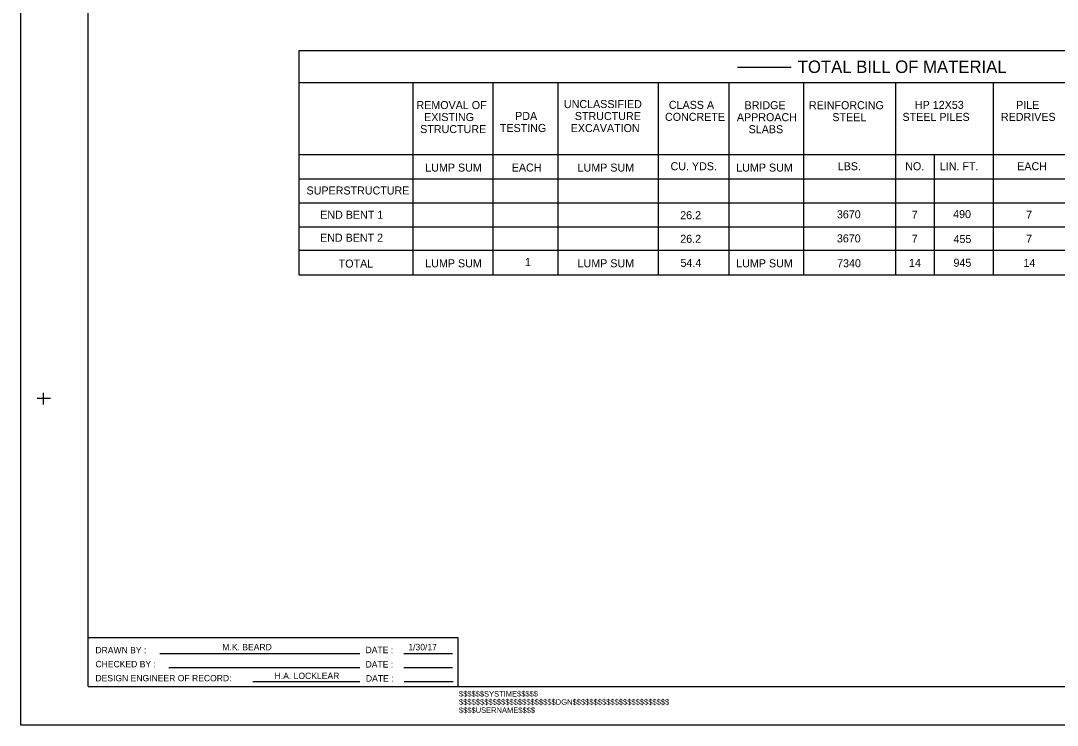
# Model space of a CAD drawing. Extents: x -20 to 509, y -659 to 21.
# Drawn here: x -19.9 to 239.1, y -658.9 to -482.9 of the extents above; entities that cross this region are included whole.
import ezdxf

# ---------------------------------------------------------------- set-up
doc = ezdxf.new("R2010")
doc.units = 0
for name, color, linetype in [('Default', 7, 'Continuous'), ('Plan Sheet CELL', 7, 'Continuous'), ('Plot Label CELL', 7, 'Continuous'), ('Plot Shape CELL', 7, 'Continuous'), ('Subtitle Text', 7, 'Continuous'), ('Text', 7, 'Continuous'), ('Typical Text General CELL', 7, 'Continuous')]:
    doc.layers.add(name, color=color, linetype=linetype)

msp = doc.modelspace()

# ---------------------------------------------------------------- linework, layer by layer
at = {"layer": 'Default'}
for p, q in [((49.55, -490.36), (49.55, -546.38)), ((355.63, -490.36), (49.55, -490.36)), ((265.45, -490.36), (193.73, -490.36)), ((172.62, -494.54), (159.22, -494.54)), ((274.98, -498.35), (49.55, -498.35)), ((139.48, -498.42), (139.48, -498.42)), ((139.48, -498.42), (139.48, -498.42)), ((338.29, -498.35), (198.01, -498.35)), ((49.55, -516.28), (274.98, -516.28)), ((49.55, -516.9), (49.55, -516.9)), ((98.08, -516.27), (169.95, -516.27)), ((139.48, -516.28), (355.63, -516.28)), ((49.55, -546.38), (355.63, -546.38)), ((139.48, -546.44), (139.48, -546.44)), ((139.48, -546.44), (139.48, -546.44))]:
    msp.add_line(p, q, dxfattribs=at)
at = {"layer": 'Plan Sheet CELL'}
for p, q in [((-3.08, -649.17), (-3.08, -313.17)), ((-15.86, -577.17), (-12.5, -577.17)), ((-14.22, -578.75), (-14.22, -575.85)), ((-3.08, -636.98), (89.31, -636.98)), ((89.31, -636.98), (89.31, -649.17)), ((14.82, -640.94), (64.77, -640.94)), ((75.76, -640.94), (88, -640.94)), ((17.11, -644.45), (64.77, -644.45)), ((75.76, -644.45), (88, -644.45)), ((-3.08, -649.17), (508.93, -649.17)), ((38.08, -647.96), (64.77, -647.96)), ((38.08, -647.96), (64.77, -647.96)), ((75.85, -647.96), (88.09, -647.96)), ((75.85, -647.96), (88.09, -647.96)), ((-19.94, -658.86), (-19.94, -658.86))]:
    msp.add_line(p, q, dxfattribs=at)
at = {"layer": 'Plot Shape CELL'}
msp.add_lwpolyline([(-19.94, -306.87), (509.07, -306.87), (509.07, -658.86), (-19.94, -658.86)], close=True, dxfattribs=at)
at = {"layer": 'Typical Text General CELL'}
for p, q in [((78.09, -498.35), (78.09, -546.38)), ((78.09, -498.35), (78.09, -546.38)), ((98.08, -498.35), (98.08, -546.38)), ((98.08, -498.35), (98.08, -546.38)), ((114.27, -498.35), (114.27, -546.38)), ((139.48, -546.38), (139.48, -498.35)), ((157.04, -498.35), (157.04, -546.38)), ((175.68, -498.35), (175.68, -546.38)), ((198.7, -498.35), (198.7, -546.38)), ((198.7, -498.35), (198.7, -546.38)), ((223.09, -498.35), (223.09, -546.38)), ((208.33, -516.28), (208.33, -546.38)), ((49.55, -522.4), (274.98, -522.4)), ((139.48, -522.4), (355.63, -522.4)), ((49.55, -528.33), (274.98, -528.33)), ((139.48, -528.33), (355.63, -528.33)), ((49.55, -534.39), (355.63, -534.39)), ((49.55, -540.19), (274.98, -540.19)), ((139.48, -540.19), (355.63, -540.19))]:
    msp.add_line(p, q, dxfattribs=at)

# ---------------------------------------------------------------- texts
at = {"layer": 'Default'}
for s, height, p in [('TOTAL BILL OF MATERIAL', 3.1223, (174.24, -495.92)), ('REMOVAL OF', 2, (78.96, -504.93)), ('UNCLASSIFIED', 2, (115.81, -504.68)), ('CLASS A', 2, (142.04, -504.88)), ('BRIDGE', 2, (160.95, -504.96)), ('REINFORCING', 2, (177.04, -504.96)), ('HP 12X53', 2, (203.53, -504.88)), ('PILE', 2, (228.82, -504.88)), ('EXISTING', 2, (80.86, -507.93)), ('PDA', 2, (103.62, -507.65)), ('STRUCTURE', 2, (118.54, -507.68)), ('CONCRETE', 2, (141.07, -507.88)), ('APPROACH', 2, (159.03, -507.96)), ('STEEL', 2, (182.89, -507.96)), ('STEEL PILES', 2, (200.42, -507.88)), ('REDRIVES', 2, (225.02, -507.88)), ('STRUCTURE ', 2, (79.89, -510.93)), ('TESTING', 2, (99.8, -510.65)), ('EXCAVATION', 2, (117.5, -510.68)), ('SLABS', 2, (161.97, -510.96)), ('LUMP SUM', 2, (81.16, -520.55)), ('EACH', 2, (102.77, -520.54)), ('LUMP SUM', 2, (119.23, -520.55)), ('CU. YDS.', 2, (142.46, -520.21)), ('LUMP SUM', 2, (158.88, -520.55)), ('LBS.', 2, (184.24, -520.21)), ('NO.', 2, (201.1, -520.21)), ('LIN. FT.', 2, (209.75, -520.21)), ('EACH', 2, (229.1, -520.21)), ('LUMP SUM', 2, (81.16, -544.46)), ('LUMP SUM', 2, (119.23, -544.46)), ('LUMP SUM', 2, (158.88, -544.46))]:
    msp.add_text(s, height=height, dxfattribs=at).set_placement(p)
at = {"layer": 'Plan Sheet CELL'}
for s, height, p in [('DRAWN BY :', 1.6, (-1.27, -640.91)), ('DATE :', 1.6, (66.24, -640.86)), ('CHECKED BY :', 1.5999, (-1.27, -644.38)), ('DATE :', 1.6, (66.24, -644.44)), ('DESIGN ENGINEER OF RECORD:', 1.5999, (-1.27, -647.89)), ('DATE :', 1.6, (66.33, -647.95))]:
    msp.add_text(s, height=height, dxfattribs=at).set_placement(p)
at = {"layer": 'Plot Label CELL'}
for s, height, p in [('$$$$$$SYSTIME$$$$$', 1.3606, (89.58, -651.69)), ('$$$$$$$$$$$$$$$$$$$$$$$DGN$$$$$$$$$$$$$$$$$$$$$$$', 1.3689, (89.58, -653.73)), ('$$$$USERNAME$$$$', 1.3606, (89.58, -655.77))]:
    msp.add_text(s, height=height, dxfattribs=at).set_placement(p)
at = {"layer": 'Subtitle Text'}
for s, height, p in [('M.K. BEARD', 1.6, (30.44, -640.13)), ('1/30/17', 1.6, (76.93, -640.13)), ('H.A. LOCKLEAR', 1.5999, (43.51, -647.32))]:
    msp.add_text(s, height=height, dxfattribs=at).set_placement(p)
at = {"layer": 'Text'}
for s, p in [('26.2', (144.88, -532.45)), ('3670', (184.02, -532.23)), ('7', (202.71, -532.34)), ('490', (213.08, -532.17)), ('7', (231.32, -532.34)), ('3670', (184.02, -538.24)), ('26.2', (144.88, -538.34)), ('7', (202.71, -538.34)), ('455', (213.17, -538.4)), ('7', (231.32, -538.34)), ('1', (106.05, -544.17)), ('54.4', (144.94, -544.35)), ('7340', (184.08, -544.45)), ('14', (202.05, -544.35)), ('945', (213.16, -544.32)), ('14', (230.66, -544.35))]:
    msp.add_text(s, height=2, dxfattribs=at).set_placement(p)
at = {"layer": 'Typical Text General CELL'}
for s, p in [('SUPERSTRUCTURE', (51.49, -526.27)), ('END BENT 1', (54.9, -532.33)), ('END BENT 2', (54.87, -538.07)), ('TOTAL', (59.52, -544.53))]:
    msp.add_text(s, height=2, dxfattribs=at).set_placement(p)

doc.saveas('drawing.dxf')
